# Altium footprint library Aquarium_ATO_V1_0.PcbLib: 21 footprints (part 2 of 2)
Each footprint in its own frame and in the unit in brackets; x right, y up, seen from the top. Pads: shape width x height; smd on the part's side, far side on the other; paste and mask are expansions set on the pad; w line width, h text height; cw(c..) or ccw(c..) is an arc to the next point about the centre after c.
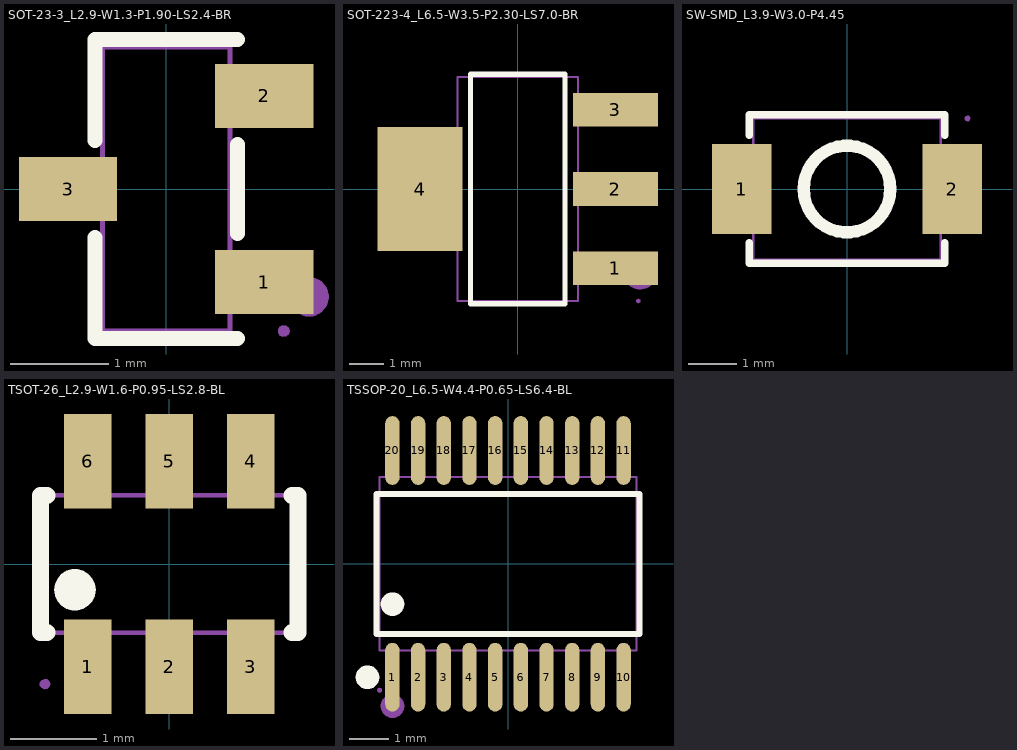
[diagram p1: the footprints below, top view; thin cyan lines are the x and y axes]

## SOT-23-3_L2.9-W1.3-P1.90-LS2.4-BR [mil]
pads (3):
  rect 39.4x25.6 smd: 1(39.4,-37.4) 2(39.4,37.4) 3(-39.4,0)
Top Overlay:
  lines w6: -28.6,-19.5 -28.6,-60.1 28.6,-60.1 ; -28.6,19.5 -28.6,60.1 28.6,60.1 ; 28.6,-17.9 28.6,17.9
Mechanical 6:
  lines w7.9: 53.5,-43.3 53.9,-41.6 55,-40.2 56.6,-39.5 58.4,-39.5 59.9,-40.2 61,-41.6 61.4,-43.3 61,-45 59.9,-46.4 58.4,-47.2 56.6,-47.2 55,-46.4 53.9,-45 53.5,-43.3
Mechanical 7:
  lines w2: -25.6,-57.1 25.6,-57.1 25.6,57.1 -25.6,57.1 -25.6,-57.1
Mechanical 8:
  region: 49.6,-57.1 49.2,-58.4 48.2,-59.2 46.9,-59.4 45.7,-58.9 45,-57.8 45,-56.4 45.7,-55.3 46.9,-54.8 48.2,-54.9 49.2,-55.8
Mechanical 9:
  region: -47.2,-8.5 -47.2,8.5 -35.4,8.5 -35.4,-8.5
  region: 35.4,-45.9 35.4,-28.9 47.2,-28.9 47.2,-45.9
  region: 35.4,28.9 35.4,45.9 47.2,45.9 47.2,28.9
Mechanical 10:
  region: -35.8,-8.5 -35.8,8.5 -25.2,8.5 -25.2,-8.5
  region: 25.2,-45.9 25.2,-28.9 35.8,-28.9 35.8,-45.9
  region: 25.2,28.9 25.2,45.9 35.8,45.9 35.8,28.9

## SOT-223-4_L6.5-W3.5-P2.30-LS7.0-BR [mil]
pads (4):
  rect 97.2x38.6 smd: 1(111.6,-90.6) 2(111.6,0) 3(111.6,90.6)
  rect 97.2x141.7 smd: 4(-111.6,0)
Top Overlay:
  lines w6: -54,-131 54,-131 54,131 -54,131 -54,-131
Mechanical 6:
  lines w19.7: 130.2,-96.3 130.2,-93.7 131,-91.1 132.4,-88.8 134.3,-87 136.7,-85.7 139.3,-85.2 142,-85.4 144.5,-86.3 146.7,-87.8 148.4,-89.9 149.5,-92.3 149.8,-95 149.5,-97.7 148.4,-100.1 146.7,-102.2 144.5,-103.7 142,-104.6 139.3,-104.8 136.7,-104.3 134.3,-103 132.4,-101.2 131,-98.9 130.2,-96.3
Mechanical 7:
  lines w2: -68.9,-128 68.9,-128 68.9,128 -68.9,128 -68.9,-128
Mechanical 8:
  region: 140.2,-127.9 139.8,-129.2 138.8,-130.1 137.5,-130.3 136.3,-129.7 135.5,-128.6 135.5,-127.3 136.3,-126.2 137.5,-125.6 138.8,-125.8 139.8,-126.7
Mechanical 9:
  region: -100.4,-59.1 -100.4,59.1 -137.8,59.1 -137.8,-59.1
  region: 100.4,76.8 100.4,104.3 137.8,104.3 137.8,76.8
  region: 100.4,-13.8 100.4,13.8 137.8,13.8 137.8,-13.8
  region: 100.4,-104.3 100.4,-76.8 137.8,-76.8 137.8,-104.3
Mechanical 10:
  region: -100.8,-59.1 -100.8,59.1 -68.5,59.1 -68.5,-59.1
  region: 68.5,76.8 68.5,104.3 100.8,104.3 100.8,76.8
  region: 68.5,-13.8 68.5,13.8 100.8,13.8 100.8,-13.8
  region: 68.5,-104.3 68.5,-76.8 100.8,-76.8 100.8,-104.3

## SW-SMD_L3.9-W3.0-P4.45 [mil]
pads (2):
  rect 48.4x73.2 smd: 1(-86,0) 2(86,0)
Top Overlay:
  lines w6: -79.8,-43.7 -79.8,-60.7 79.8,-60.7 79.8,-43.7 ; -79.8,43.7 -79.8,60.7 79.8,60.7 79.8,43.7
  lines w10: -35.4,0 -35,5.3 -33.9,10.4 -31.9,15.4 -29.3,20 -26,24.1 -22.1,27.7 -17.7,30.7 -12.9,33 -7.9,34.5 -2.6,35.3 2.6,35.3 7.9,34.5 12.9,33 17.7,30.7 22.1,27.7 26,24.1 29.3,20 31.9,15.4 33.9,10.4 35,5.3 35.4,0 35,-5.3 33.9,-10.4 31.9,-15.4 29.3,-20 26,-24.1 22.1,-27.7 17.7,-30.7 12.9,-33 7.9,-34.5 2.6,-35.3 -2.6,-35.3 -7.9,-34.5 -12.9,-33 -17.7,-30.7 -22.1,-27.7 -26,-24.1 -29.3,-20 -31.9,-15.4 -33.9,-10.4 -35,-5.3 -35.4,0
Mechanical 7:
  lines w2: -76.8,-57.7 -76.8,57.7 76.8,57.7 76.8,-57.7 -76.8,-57.7
Mechanical 8:
  region: 100.8,57.7 100.4,56.4 99.4,55.5 98.1,55.3 96.9,55.9 96.2,57 96.2,58.3 96.9,59.5 98.1,60 99.4,59.8 100.4,59
Mechanical 9:
  region: -98.4,25.6 -98.4,-25.6 -63,-25.6 -63,25.6
  region: 98.4,25.6 98.4,-25.6 63,-25.6 63,25.6

## TSOT-26_L2.9-W1.6-P0.95-LS2.8-BL [mil]
pads (6):
  rect 21.7x43.3 smd paste+0 mask+2: 1(-37.4,-47.2) 2(0,-47.2) 3(37.4,-47.2) 4(37.4,47.2) 5(0,47.2) 6(-37.4,47.2)
Top Overlay:
  region: -52.8,-11.8 -52.4,-9.1 -51.3,-6.7 -49.5,-4.6 -47.3,-3.2 -44.7,-2.4 -42,-2.4 -39.4,-3.2 -37.1,-4.6 -35.3,-6.7 -34.2,-9.1 -33.8,-11.8 -34.2,-14.5 -35.3,-17 -37.1,-19 -39.4,-20.5 -42,-21.2 -44.7,-21.2 -47.3,-20.5 -49.5,-19 -51.3,-17 -52.4,-14.5
  lines w7.9: -56.3,-31.5 -59.1,-31.5 -59.1,-22.5 -59.1,22.5 -59.1,31.5 -56.3,31.5 ; 56.3,-31.5 59.1,-31.5 59.1,-22.5 59.1,22.5 59.1,31.5 56.3,31.5
Mechanical 6:
  lines w7.9: -43.3,-55.1 -42.9,-53.4 -41.8,-52 -40.2,-51.3 -38.5,-51.3 -36.9,-52 -35.8,-53.4 -35.4,-55.1 -35.8,-56.8 -36.9,-58.2 -38.5,-59 -40.2,-59 -41.8,-58.2 -42.9,-56.8 -43.3,-55.1
Mechanical 7:
  lines w2: -57.1,-31.5 57.1,-31.5 57.1,31.5 -57.1,31.5 -57.1,-31.5
Mechanical 8:
  region: -54.7,-55.1 -55.1,-56.4 -56.1,-57.3 -57.4,-57.5 -58.6,-56.9 -59.4,-55.8 -59.4,-54.5 -58.6,-53.3 -57.4,-52.8 -56.1,-53 -55.1,-53.8
Mechanical 9:
  region: -46.1,39.4 -46.1,55.1 -28.7,55.1 -28.7,39.4
  region: -8.7,39.4 -8.7,55.1 8.7,55.1 8.7,39.4
  region: 28.7,39.4 28.7,55.1 46.1,55.1 46.1,39.4
  region: 28.7,-55.1 28.7,-39.4 46.1,-39.4 46.1,-55.1
  region: -8.7,-55.1 -8.7,-39.4 8.7,-39.4 8.7,-55.1
  region: -46.1,-55.1 -46.1,-39.4 -28.7,-39.4 -28.7,-55.1
Mechanical 10:
  region: -46.1,31.1 -46.1,39.8 -28.7,39.8 -28.7,31.1
  region: -8.7,31.1 -8.7,39.8 8.7,39.8 8.7,31.1
  region: 28.7,31.1 28.7,39.8 46.1,39.8 46.1,31.1
  region: 28.7,-39.8 28.7,-31.1 46.1,-31.1 46.1,-39.8
  region: -8.7,-39.8 -8.7,-31.1 8.7,-31.1 8.7,-39.8
  region: -46.1,-39.8 -46.1,-31.1 -28.7,-31.1 -28.7,-39.8

## TSSOP-20_L6.5-W4.4-P0.65-LS6.4-BL [mil]
pads (20):
  oval 14.3x68.6 smd: 1(-115.2,-113) 2(-89.6,-113) 3(-64,-113) 4(-38.4,-113) 5(-12.8,-113) 6(12.8,-113) 7(38.4,-113) 8(64,-113) 9(89.6,-113) 10(115.2,-113) 11(115.2,113) 12(89.6,113) 13(64,113) 14(38.4,113) 15(12.8,113) 16(-12.8,113) 17(-38.4,113) 18(-64,113) 19(-89.6,113) 20(-115.2,113)
Top Overlay:
  lines w6: -131,-69.7 131,-69.7 131,69.7 -131,69.7 -131,-69.7
  lines w11.8: -146,-113 -145.7,-111 -144.7,-109.2 -143.1,-107.9 -141.2,-107.2 -139.1,-107.2 -137.2,-107.9 -135.6,-109.2 -134.6,-111 -134.2,-113 -134.6,-115.1 -135.6,-116.8 -137.2,-118.1 -139.1,-118.9 -141.2,-118.9 -143.1,-118.1 -144.7,-116.8 -145.7,-115.1 -146,-113 ; -121.1,-40.1 -120.7,-38.1 -119.7,-36.3 -118.1,-35 -116.2,-34.3 -114.1,-34.3 -112.2,-35 -110.6,-36.3 -109.6,-38.1 -109.3,-40.1 -109.6,-42.1 -110.6,-43.9 -112.2,-45.2 -114.1,-45.9 -116.2,-45.9 -118.1,-45.2 -119.7,-43.9 -120.7,-42.1 -121.1,-40.1
Mechanical 6:
  lines w11.8: -121.1,-141.7 -120.7,-139.7 -119.7,-137.9 -118.1,-136.6 -116.2,-135.9 -114.1,-135.9 -112.2,-136.6 -110.6,-137.9 -109.6,-139.7 -109.3,-141.7 -109.6,-143.8 -110.6,-145.5 -112.2,-146.8 -114.1,-147.6 -116.2,-147.6 -118.1,-146.8 -119.7,-145.5 -120.7,-143.8 -121.1,-141.7
Mechanical 7:
  lines w2: -128,-86.6 128,-86.6 128,86.6 -128,86.6 -128,-86.6
Mechanical 8:
  region: -125.6,-126 -126,-127.3 -127,-128.1 -128.3,-128.3 -129.5,-127.8 -130.2,-126.6 -130.2,-125.3 -129.5,-124.2 -128.3,-123.6 -127,-123.8 -126,-124.7
Mechanical 9:
  region: 110,126 110,102.4 120.3,102.4 120.3,126
  region: 84.4,126 84.4,102.4 94.7,102.4 94.7,126
  region: 58.9,126 58.9,102.4 69.1,102.4 69.1,126
  region: 33.3,126 33.3,102.4 43.5,102.4 43.5,126
  region: 7.7,126 7.7,102.4 17.9,102.4 17.9,126
  region: -17.9,126 -17.9,102.4 -7.7,102.4 -7.7,126
  region: -43.5,126 -43.5,102.4 -33.3,102.4 -33.3,126
  region: -69.1,126 -69.1,102.4 -58.9,102.4 -58.9,126
  region: -94.7,126 -94.7,102.4 -84.4,102.4 -84.4,126
  region: -120.3,126 -120.3,102.4 -110,102.4 -110,126
  region: 110,-126 110,-102.4 120.3,-102.4 120.3,-126
  region: 84.4,-126 84.4,-102.4 94.7,-102.4 94.7,-126
  region: 58.9,-126 58.9,-102.4 69.1,-102.4 69.1,-126
  region: 33.3,-126 33.3,-102.4 43.5,-102.4 43.5,-126
  region: 7.7,-126 7.7,-102.4 17.9,-102.4 17.9,-126
  region: -17.9,-126 -17.9,-102.4 -7.7,-102.4 -7.7,-126
  region: -43.5,-126 -43.5,-102.4 -33.3,-102.4 -33.3,-126
  region: -69.1,-126 -69.1,-102.4 -58.9,-102.4 -58.9,-126
  region: -94.7,-126 -94.7,-102.4 -84.4,-102.4 -84.4,-126
  region: -120.3,-126 -120.3,-102.4 -110,-102.4 -110,-126
Mechanical 10:
  region: 110,102.8 110,86.2 120.3,86.2 120.3,102.8
  region: 84.4,102.8 84.4,86.2 94.7,86.2 94.7,102.8
  region: 58.9,102.8 58.9,86.2 69.1,86.2 69.1,102.8
  region: 33.3,102.8 33.3,86.2 43.5,86.2 43.5,102.8
  region: 7.7,102.8 7.7,86.2 17.9,86.2 17.9,102.8
  region: -17.9,102.8 -17.9,86.2 -7.7,86.2 -7.7,102.8
  region: -43.5,102.8 -43.5,86.2 -33.3,86.2 -33.3,102.8
  region: -69.1,102.8 -69.1,86.2 -58.9,86.2 -58.9,102.8
  region: -94.7,102.8 -94.7,86.2 -84.4,86.2 -84.4,102.8
  region: -120.3,102.8 -120.3,86.2 -110,86.2 -110,102.8
  region: 110,-102.8 110,-86.2 120.3,-86.2 120.3,-102.8
  region: 84.4,-102.8 84.4,-86.2 94.7,-86.2 94.7,-102.8
  region: 58.9,-102.8 58.9,-86.2 69.1,-86.2 69.1,-102.8
  region: 33.3,-102.8 33.3,-86.2 43.5,-86.2 43.5,-102.8
  region: 7.7,-102.8 7.7,-86.2 17.9,-86.2 17.9,-102.8
  region: -17.9,-102.8 -17.9,-86.2 -7.7,-86.2 -7.7,-102.8
  region: -43.5,-102.8 -43.5,-86.2 -33.3,-86.2 -33.3,-102.8
  region: -69.1,-102.8 -69.1,-86.2 -58.9,-86.2 -58.9,-102.8
  region: -94.7,-102.8 -94.7,-86.2 -84.4,-86.2 -84.4,-102.8
  region: -120.3,-102.8 -120.3,-86.2 -110,-86.2 -110,-102.8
